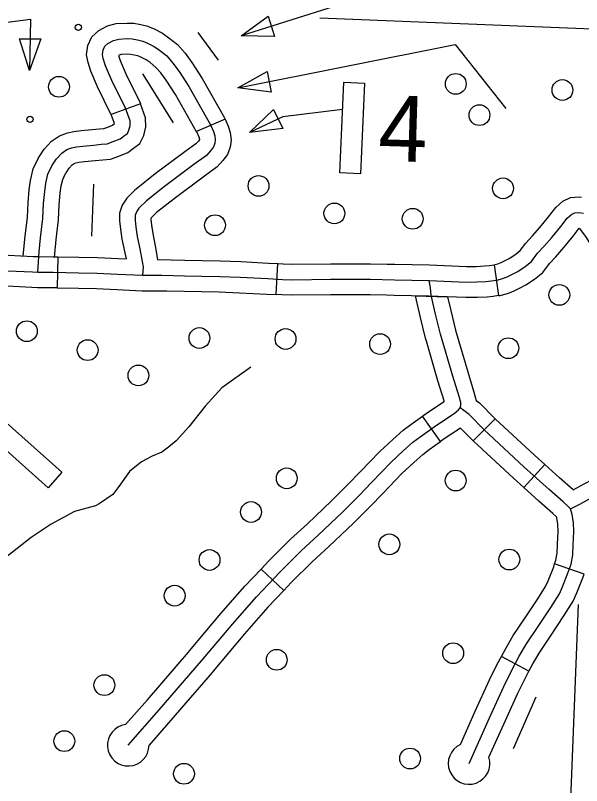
# Model space of a CAD drawing. Extents: x 653372 to 905732, y 627442 to 787275.
# Drawn here: x 666359 to 669082, y 766220 to 769926 of the extents above; entities that cross this region are included whole.
import ezdxf

# ---------------------------------------------------------------- set-up
doc = ezdxf.new("R2010")
doc.units = 0
for name, color, linetype in [('31', 7, 'Continuous'), ('32', 7, 'Continuous'), ('35', 7, 'Continuous'), ('5', 7, 'Continuous'), ('56', 7, 'Continuous')]:
    doc.layers.add(name, color=color, linetype=linetype)

msp = doc.modelspace()

# ---------------------------------------------------------------- linework, layer by layer
at = {"layer": '31'}
for p, q in [((666960.1, 769500.6), (666819.1, 769449.2)), ((666960.1, 769500.6), (666960.1, 769500.6)), ((667368, 769426.1), (667229.9, 769367.5)), ((666562.7, 768764.4), (666560.5, 768614.5)), ((667612.8, 768582.3), (667621.2, 768732.1)), ((667621.2, 768732.1), (667621.2, 768732.1)), ((668662.1, 768726.2), (668682.3, 768577.6)), ((668403.6, 767875.7), (668316.2, 767997.6)), ((668316.2, 767997.6), (668316.2, 767997.6)), ((668666.8, 767984.7), (668560, 767879.4)), ((667540.9, 767261.6), (667650, 767158.7))]:
    msp.add_line(p, q, dxfattribs=at)
for points in [[(666819.1, 769449.2), (666818.8, 769450.2), (666754.4, 769581.9), (666721.5, 769657.4), (666709, 769699.8), (666701, 769736.3), (666707.8, 769782.2), (666727.1, 769823.6), (666759.7, 769852.9), (666802.5, 769875.7), (666844.3, 769886.9), (666896.7, 769889.4), (666928.5, 769888.4), (666962.7, 769882.3), (666996.2, 769873.7), (667005.8, 769869.7)], [(667005.8, 769869.7), (667026.4, 769860.9), (667065.8, 769840.9), (667096.8, 769818.6), (667138.5, 769785.6), (667175.4, 769743.9), (667208, 769699.1), (667257.9, 769622.7), (667365.1, 769433), (667368, 769426.1)], [(666466.9, 768690.6), (666473.8, 768787.8), (666480.3, 768855.1), (666491.4, 768948.4), (666494.8, 769020.3), (666500.4, 769078.7), (666505.4, 769119), (666515.6, 769162), (666534.6, 769201.5), (666557.3, 769236.5), (666582.4, 769263.8), (666606.4, 769280.3), (666629.6, 769289.1), (666652.6, 769293.5), (666684, 769297.7), (666735.7, 769301.9), (666771.4, 769305.9), (666800.8, 769308.8), (666829.6, 769318.7), (666862.5, 769332.4), (666883.3, 769347.7), (666898.3, 769358.7), (666905.1, 769373.2), (666910.9, 769397.2), (666910.2, 769418.2), (666887.9, 769479.6), (666822.5, 769613.4), (666792.1, 769683.1), (666781.7, 769718.4), (666777.2, 769738.9), (666780.4, 769760.5), (666788.6, 769778.1), (666803, 769791), (666830.2, 769805.5), (666855.9, 769812.4), (666897.3, 769814.3), (666920.8, 769813.6), (666946.8, 769809), (666972.1, 769802.5), (666994.7, 769792.9), (667026.7, 769776.7), (667051.6, 769758.7), (667086.7, 769730.9), (667116.9, 769696.9), (667146.3, 769656.5), (667193.7, 769583.8), (667297.7, 769399.8), (667311.4, 769367.5), (667318.4, 769346.3), (667320.4, 769327.8), (667318, 769310.6), (667311.7, 769293.6), (667297.8, 769274.9), (667278.7, 769252.3), (667217.5, 769208.3), (667076.2, 769103.6), (666988.8, 769034.3), (666952.7, 768999.1), (666940.7, 768980.3), (666935.1, 768962.7), (666935.1, 768940.9), (666938.5, 768907.7), (666945.4, 768862.9), (666957.7, 768803.3), (666967.9, 768742.5), (666972.9, 768716.2), (666971, 768676.1)], [(666947.2, 769731.6), (666948, 769731.3), (666930.9, 769735.6), (666913.1, 769738.8), (666897.9, 769739.2), (666867.4, 769737.8), (666857.9, 769735.3), (666855.3, 769733.9), (666862.8, 769708.7), (666890.6, 769644.8), (666957, 769509), (666960.1, 769500.6)], [(667229.9, 769367.5), (667230.3, 769366.6), (667129.6, 769544.8), (667084.5, 769613.9), (667058.4, 769649.8), (667035, 769676.2), (667006.4, 769698.8), (666987.6, 769712.4), (666963, 769724.9), (666947.2, 769731.6)], [(666602.8, 769168.8), (666616.9, 769190.4), (666631.8, 769206.8), (666641.5, 769213.4), (666650.2, 769216.7), (666664.6, 769219.5), (666691.9, 769223.1), (666742.9, 769227.2), (666779.4, 769231.3), (666817, 769235.1), (666856.2, 769248.6), (666899.6, 769266.6), (666927.7, 769287.3), (666958, 769309.6), (666976.2, 769348.1), (666986.1, 769389.4), (666984.8, 769432.6), (666960.1, 769500.6)], [(666477, 769250.4), (666497.8, 769282.6), (666532.9, 769320.8), (666571.4, 769347.2), (666609, 769361.6), (666640.7, 769367.6), (666676, 769372.3), (666728.5, 769376.5), (666763.5, 769380.5), (666784.6, 769382.6), (666802.9, 769388.9), (666825.3, 769398.2), (666835.1, 769405.4), (666819.1, 769449.2)], [(667368, 769426.1), (667381.7, 769393.9), (667392.1, 769362.2), (667396, 769326.5), (667391.1, 769292.3), (667378.4, 769257.5), (667356.5, 769228.2), (667329.9, 769196.8), (667261.7, 769147.7), (667121.8, 769044.1), (667038.4, 768977.9), (667038.3, 768977.8)], [(667229.9, 769367.5), (667241.1, 769341.1), (667244.7, 769330.4), (667244.8, 769329.3), (667239.1, 769321.6), (667227.4, 769307.8), (667173.3, 769268.9), (667030.5, 769163.2), (666939.2, 769090.7), (666933.5, 769085.1)], [(666396.7, 768769.1), (666405.7, 768863.1), (666416.6, 768954.6), (666420, 769025.6), (666425.8, 769086.9), (666431.5, 769132.3), (666444.5, 769187.2), (666469.1, 769238.3), (666477, 769250.4)], [(666546.7, 768761.8), (666554.9, 768847.1), (666566.2, 768942.2), (666569.7, 769014.9), (666575, 769070.5), (666579.3, 769105.6), (666586.7, 769136.8), (666600.2, 769164.7), (666602.8, 769168.8)], [(666933.5, 769085.1), (666894.2, 769046.8), (666872.2, 769012.5), (666860.1, 768974.4), (666860.1, 768937), (666864.1, 768898), (666871.6, 768849.6), (666891.1, 768754.7)], [(668660.2, 768726), (668678.7, 768731.1), (668694.8, 768737.2), (668715.1, 768747.1), (668736.2, 768758.7), (668766.9, 768778.6), (668786.1, 768794.3), (668813, 768829.6), (668846, 768865.4), (668881.6, 768905.8), (668923.4, 768956.8), (668958.4, 769002.3), (668992.4, 769031.5), (669028.6, 769050.5), (669071, 769053.6), (669081.8, 769051.7)], [(667038.3, 768977.8), (667011.2, 768951.4), (667010.1, 768949.6), (667010.1, 768944.8), (667012.9, 768917.3), (667019.3, 768876.2), (667031.4, 768817.1), (667042.5, 768751.4)], [(668348.8, 768650.2), (668526.5, 768643.1), (668578.8, 768643.3), (668622, 768645.7), (668647.7, 768648.6), (668675.4, 768652.3), (668702.2, 768659.8), (668724.5, 768668.3), (668749.6, 768680.4), (668774.8, 768694.3), (668811.2, 768718), (668840.4, 768741.9), (668870.5, 768781.3), (668901.7, 768815.2), (668938.8, 768857.2), (668982.1, 768910.1), (669013.1, 768950.4), (669034.8, 768969), (669049.7, 768976.8), (669067.1, 768978.1), (669091.3, 768973.8)], [(668682.3, 768577.6), (668690.5, 768578.7), (668725.7, 768588.5), (668754.1, 768599.4), (668784, 768613.7), (668813.4, 768630), (668855.6, 768657.3), (668894.7, 768689.4), (668928, 768733), (668957.5, 768765), (668995.9, 768808.6), (669040.8, 768863.5), (669070.5, 768902.1)], [(669070.5, 768902.1), (669101.2, 768862), (669127.9, 768818.8), (669152.7, 768777.6), (669180, 768731), (669216, 768678.1), (669238.9, 768650.5), (669270.2, 768613.8), (669305.7, 768586.9), (669336.5, 768565.4), (669365.9, 768552.9), (669387.3, 768541.3), (669401.2, 768537)], [(666034.8, 768784.8), (666091.6, 768784.3), (666149.9, 768783.1), (666219.2, 768780), (666326.3, 768772.6), (666445.1, 768766.7), (666469.1, 768765.6), (666541.2, 768764.8), (666562.7, 768764.4)], [(666562.7, 768764.4), (666664.5, 768762.9), (666754.2, 768761.2), (666853.8, 768756.3), (666891.1, 768754.7)], [(667042.5, 768751.4), (667174.5, 768748.6), (667257.3, 768747), (667343.7, 768745.3), (667443.6, 768741.4), (667576.3, 768734.6), (667621.2, 768732.1)], [(667621.2, 768732.1), (667647.2, 768730.6), (667693.4, 768729.2), (667874.1, 768731.2), (668066.4, 768731.1), (668146.5, 768729.3)], [(668146.5, 768729.3), (668184.4, 768728.5), (668351.1, 768725.2), (668527.8, 768718.1), (668576.5, 768718.3), (668615.7, 768720.5), (668638.5, 768723), (668662.1, 768726.2)], [(666321.9, 768697.7), (666441.4, 768691.8), (666466.9, 768690.6), (666540.2, 768689.8), (666663.2, 768687.9), (666751.7, 768686.2), (666850.3, 768681.4), (666971, 768676.1), (667064, 768675.9), (667173, 768673.6), (667255.8, 768672), (667341.5, 768670.4), (667440.2, 768666.5), (667572.3, 768659.7), (667643.9, 768655.7), (667692.7, 768654.2), (667874.5, 768656.2), (668065.5, 768656.1), (668182.9, 768653.5), (668348.8, 768650.2)], [(666560.5, 768614.5), (666539.3, 768614.8), (666464.7, 768615.6), (666437.8, 768616.9), (666317.4, 768622.9), (666210.7, 768630.2), (666145, 768633.1), (666089.3, 768634.3), (666033.5, 768634.8)], [(666901.7, 766414.1), (667050.6, 766583.7), (667253.4, 766819.4), (667404.3, 766998.7), (667518.2, 767128.4), (667631.9, 767248.7), (667734.4, 767351.3), (667815.1, 767425.2), (667932.1, 767536.3), (668011.7, 767615.5), (668071.2, 767678), (668164.6, 767774.6), (668224, 767830.5), (668270.5, 767871.8), (668305, 767897.4), (668383.5, 767953.6), (668468.6, 768009.6), (668490.4, 768028.5), (668498.7, 768038), (668501.7, 768049.5), (668500.4, 768063.7), (668492.4, 768092.4), (668462.4, 768189.3), (668403.7, 768392.6), (668380, 768489.2), (668358.8, 768579.5), (668354.5, 768615.1), (668348.8, 768650.2)], [(666560.5, 768614.5), (666661.9, 768613), (666749.1, 768611.3), (666846.8, 768606.5), (666969.3, 768601.1), (667063.1, 768600.9), (667087.7, 768600.4)], [(667087.7, 768600.4), (667171.4, 768598.6), (667254.4, 768597), (667339.3, 768595.4), (667436.8, 768591.6), (667568.3, 768584.8), (667612.8, 768582.3)], [(668143.2, 768579.4), (668064.7, 768581.1), (667874.9, 768581.2), (667692, 768579.2), (667640.7, 768580.8), (667612.8, 768582.3)], [(668682.3, 768577.6), (668657, 768574.2), (668628.2, 768570.9), (668581, 768568.3), (668525.2, 768568), (668346.6, 768575.3), (668181.3, 768578.5), (668143.2, 768579.4)], [(668335.4, 768359), (668331.3, 768373.3), (668307.1, 768471.7), (668282.4, 768576.5), (668437.7, 768571.6)], [(668437.7, 768571.6), (668452.9, 768506.7), (668476.2, 768412), (668479.5, 768400.6)], [(668479.5, 768400.6), (668534.3, 768210.8), (668564.3, 768113.5), (668575.5, 768073.7)], [(668316.2, 767997.6), (668341, 768015.4), (668421.2, 768068.3), (668420.4, 768071.2), (668390.6, 768167.9), (668335.4, 768359)], [(668575.5, 768073.7), (668590.8, 768061.7), (668666.8, 767984.7)], [(668613.4, 767932), (668540.9, 768005.5), (668516.1, 768024.8), (668498.7, 768038)], [(667921.1, 767631.2), (667958.1, 767668), (668017.1, 767729.9), (668111.9, 767828), (668173.4, 767885.9), (668223.2, 767930), (668260.8, 767958), (668316.2, 767997.6)], [(668499.8, 767940.4), (668425.9, 767891.8), (668403.6, 767875.7)], [(668560, 767879.4), (668499.8, 767940.4)], [(668026.9, 767524.9), (668065.3, 767563.1), (668125.3, 767626), (668217.4, 767721.2), (668274.6, 767775.2), (668317.8, 767813.5), (668349.2, 767836.8), (668403.6, 767875.7)], [(667540.9, 767261.6), (667578.1, 767301), (667682.5, 767405.5), (667764, 767480.1), (667879.8, 767590), (667921.1, 767631.2)], [(667650, 767158.7), (667685.7, 767196.5), (667786.3, 767297.1), (667866.3, 767370.4), (667984.4, 767482.5), (668026.9, 767524.9)], [(667190.9, 766861.8), (667196.3, 766868), (667347.4, 767047.6), (667462.8, 767178.9), (667540.9, 767261.6)], [(667650, 767158.7), (667573.7, 767077.9), (667461.2, 766949.8), (667310.5, 766770.8), (667304.6, 766764)], [(666889, 766513.3), (666994, 766632.9), (667190.9, 766861.8)], [(667304.6, 766764), (667107.2, 766534.5), (667001.7, 766414.4)]]:
    msp.add_lwpolyline(points, dxfattribs=at)
msp.add_arc((666901.7, 766414.1), 100, 97.3056, 0.1241, dxfattribs=at)
at = {"layer": '32'}
for p, q in [((668904.9, 767764.8), (668804.3, 767653.5)), ((669094.2, 767237.5), (668952.4, 767286.3)), ((668828.5, 766769.7), (668696.1, 766840.3))]:
    msp.add_line(p, q, dxfattribs=at)
for points in [[(669028.1, 767551.1), (669072.8, 767573.4), (669130.9, 767606.4), (669204, 767645.3), (669245.4, 767668.6), (669297.9, 767698.3), (669323.9, 767717.5), (669355.1, 767742.8), (669382.5, 767767.8), (669403.5, 767788.7), (669440.7, 767831.2), (669469.9, 767859.6), (669493, 767879.6), (669516.4, 767898), (669538.9, 767912.1), (669577.6, 767932.1), (669611, 767946.4), (669660.7, 767965.2), (669709.4, 767979), (669770.8, 767994.1), (669850.7, 768005.2), (669946.6, 768015), (670059.4, 768023.5)], [(668904.9, 767764.8), (668855.5, 767809.4), (668666.8, 767984.7)], [(668540.7, 766325.9), (668639.1, 766546.5), (668707.4, 766696), (668743.2, 766769.2), (668782.4, 766842.7), (668817.1, 766902), (668873.1, 766984.7), (668934.1, 767077.5), (668975, 767142.4), (668989.7, 767176.3), (669017.9, 767246.1), (669031.4, 767285.5), (669039.6, 767329.8), (669041.7, 767378.4), (669044.3, 767442.8), (669042.2, 767484.4), (669036.5, 767525), (669028.1, 767551.1), (669015.8, 767564.8), (668993.1, 767585.3), (668925.6, 767644.9), (668804.8, 767754.1), (668613.4, 767932)], [(668804.3, 767653.5), (668754.2, 767698.9), (668560, 767879.4)], [(669042, 767642.2), (669094.8, 767672.1), (669168, 767711.1), (669208.5, 767733.9), (669257, 767761.4), (669278, 767776.8), (669306.2, 767799.7), (669330.7, 767822), (669348.7, 767840), (669386.3, 767883), (669406.3, 767902.4)], [(669042, 767642.2), (668975.6, 767700.8), (668904.9, 767764.8)], [(668952.4, 767286.3), (668958.7, 767304.6), (668964.9, 767338.3), (668966.8, 767381.6), (668969.3, 767442.4), (668967.4, 767477.2), (668963.1, 767508.2), (668961.7, 767512.5), (668943.1, 767529.4), (668875.7, 767589), (668804.3, 767653.5)], [(668696.1, 766840.3), (668716.9, 766879.3), (668753.6, 766942), (668810.7, 767026.3), (668871, 767118.1), (668908.5, 767177.6), (668920.6, 767205.3), (668947.6, 767272.3), (668952.4, 767286.3)], [(668828.5, 766769.7), (668847.9, 766806.1), (668880.6, 766862), (668935.4, 766943.1), (668997.2, 767036.9), (669041.5, 767107.3), (669058.9, 767147.3), (669088.2, 767219.9), (669094.2, 767237.5)], [(668499.1, 766416.9), (668570.8, 766577.4), (668639.6, 766728.1), (668676.4, 766803.3), (668696.1, 766840.3)], [(668636.1, 766355.7), (668707.5, 766515.7), (668775.2, 766664), (668810, 766735), (668828.5, 766769.7)]]:
    msp.add_lwpolyline(points, dxfattribs=at)
msp.add_arc((668540.7, 766325.9), 100, 114.5324, 17.3516, dxfattribs=at)
at = {"layer": '35'}
for points in [[(667490.5, 768233.4), (667351.6, 768134.4), (667271.6, 768045.4), (667193.7, 767946.9), (667133, 767878.4), (667094.7, 767849.1), (667063.5, 767824.3), (667016, 767804.6), (666966, 767778), (666908.3, 767730.5), (666857, 767659.4), (666827.7, 767620.4), (666761.2, 767575.9)], [(666761.2, 767575.9), (666744.1, 767566.6), (666642.5, 767539.2), (666530.5, 767477), (666434.9, 767414.2), (666283.7, 767296.8), (666242.1, 767237.1), (666187.4, 767133.3), (666163, 767094.8)]]:
    msp.add_lwpolyline(points, dxfattribs=at)
at = {"layer": '5'}
for points in [[(669172.9, 769858.9), (667822.8, 769912.3)], [(669064.9, 767090.4), (668966.3, 764563.5)]]:
    msp.add_lwpolyline(points, dxfattribs=at)
at = {"layer": '56'}
for p, q in [((667444, 769827.4), (667574.4, 769922.4)), ((667574.4, 769922.4), (667605.3, 769825.1)), ((666427.6, 769660.6), (666378.6, 769814.2)), ((666378.6, 769814.2), (666480.6, 769812.9)), ((666480.6, 769812.9), (666427.6, 769660.6)), ((667605.3, 769825.1), (667444, 769827.4)), ((667429.3, 769577), (667569.4, 769657)), ((667569.4, 769657), (667589.3, 769556.9)), ((667589.3, 769556.9), (667429.3, 769577)), ((667484.7, 769362.1), (667600.7, 769474.2)), ((667600.7, 769474.2), (667644.7, 769382.2)), ((667644.7, 769382.2), (667484.7, 769362.1))]:
    msp.add_line(p, q, dxfattribs=at)
for points in [[(668314.1, 770103.9), (667444, 769827.4)], [(665925.4, 769842.6), (666431.4, 769907.7), (666427.6, 769660.6)], [(667237.1, 769843.8), (667334.4, 769710.8)], [(667429.3, 769577), (668474.6, 769785.7), (668717, 769478.5)], [(666969.9, 769645.2), (667117.2, 769409.1)], [(667932.5, 769474.2), (667644.4, 769438.6), (667484.7, 769362.1)], [(666735.4, 769114.6), (666724.3, 768864.1)], [(668862.3, 766644.8), (668752.3, 766395.9)]]:
    msp.add_lwpolyline(points, dxfattribs=at)
for points in [[(667938.3, 769605.1), (668038.2, 769600.6), (668018.9, 769163.6), (667919, 769168)], [(666189.2, 767943.9), (666255.6, 768018.7), (666582.7, 767728.1), (666516.2, 767653.3)]]:
    msp.add_lwpolyline(points, close=True, dxfattribs=at)
for centre, radius in [((666662.1, 769868.8), 15), ((666568.5, 769582.6), 50), ((668476.9, 769596.8), 50), ((668989.6, 769567.1), 50), ((668590.6, 769446.4), 50), ((666429.5, 769425.8), 15), ((667528.3, 769105.6), 50), ((668704.2, 769093.9), 50), ((667893.1, 768973.4), 50), ((668269.8, 768947.4), 50), ((667319, 768916.4), 50), ((668974.7, 768581.1), 50), ((666414.1, 768406.5), 50), ((667244, 768373.5), 50), ((667658.1, 768369), 50), ((668112.8, 768344.5), 50), ((666706.4, 768315.3), 50), ((668730, 768324.7), 50), ((666950.6, 768193.7), 50), ((667664, 767698.3), 50), ((668476.5, 767687.6), 50), ((667492.2, 767536.1), 50), ((668157.3, 767380.5), 50), ((667292.6, 767305.5), 50), ((668734.3, 767307.4), 50), ((667124.9, 767133.7), 50), ((667615.9, 766825), 50), ((668464.2, 766856.6), 50), ((666787, 766703.1), 50), ((666594.3, 766433.6), 50), ((668257.1, 766349.8), 50), ((667169.7, 766276.4), 50)]:
    msp.add_circle(centre, radius, dxfattribs=at)

# ---------------------------------------------------------------- texts
msp.add_text('4', height=316.8, rotation=358.28, dxfattribs=at).set_placement((668101.1, 769226.9))

doc.saveas('drawing.dxf')
